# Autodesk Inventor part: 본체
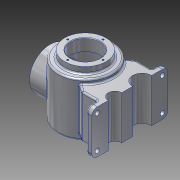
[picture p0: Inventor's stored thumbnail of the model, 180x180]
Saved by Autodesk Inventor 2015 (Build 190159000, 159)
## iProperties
Created: 2018-08
Part Number: 본체
Material: 알루미늄 6061
Document SubType Name: Modeling
Designer: line
Density: 2.7 g/cm^3
Appearance: 알루미늄 - 평지
Mass: 1879.13 g
Surface Area: 1087.48 cm^2
Volume: 695.975 cm^3
Author: line
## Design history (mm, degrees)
sketch "스케치2"
  geometry: L1 (0, 54)-(50, 54); L2 (0, 54)-(0, -54); L3 (0, 54)-(50, 54); L4 (0, 54)-(0, -54); L5 (50, -42.671)-(50, 54); A1 r 116 centre (0, 62) between (0, -54) and (50, -42.671); 1 further point
  constraints: 10 end point, 2 point on circle, 1 centre point, 1 collinear, 1 horizontal
  dimensions: "d14" = 108 vertical distance of L2.end L1.end; "d16" = 50 distance of L1.start L1.end; "d17" = 116 radius of A1; "d18" = 108 distance of L1.start L2.end; "d19" = 50 horizontal distance of L5.start A1.centre; "d20" = 62 distance of point (0, 0) A1.centre; "d21" = 8 vertical distance of L1.end A1.centre
revolve "회전1" sketch "스케치2" stored, may be unused: angle "d22" = 90 deg
sketch "스케치3"
  geometry: C1 r 38 at (0, 0); 1 further point
  constraints: 1 centre point, 1 coincident
  dimensions: "d23" = 76 diameter of C1
extrude "돌출1" join sketch "스케치3" distance "d24" = 12; taper "d25" = 0 deg
sketch "스케치4"
  geometry: C1 r 27 at (0, 0); 1 further point
  constraints: 1 centre point, 1 coincident
  dimensions: "d26" = 54 diameter of C1
extrude "돌출2" cut sketch "스케치4" distance "d27" = 22; taper "d28" = 0 deg
sketch "스케치5" dims "d29" = 65
  geometry: 3 further points
  constraints: 2 vertical alignment, 1 coincident, 2 other
hole "구멍1" sketch "스케치5" at (0, 32.5) diameter "d30" = 3.242; stored, may be unused: countersink angle "d34" = 90 deg, drill point angle "d36" = 118 deg; dims "d31" = 8, "d32" = 4, "d33" = 2, "d35" = 10
sketch "스케치6"
  geometry: L1 (0, 66)-(0, -63.544); L2 (0, 44)-(40, 44); L3 (40, 44)-(40, -36.163); L4 (0, 44)-(40, 44); L5 (40, -36.163)-(40, 44); L6 (-27, 44)-(27, 44) reference; L7 (0, 44)-(0, -44); A1 r 106 centre (0, 62) between (0, -44) and (40, -36.163); 1 further point
  constraints: 12 end point, 2 perpendicular, 2 point on circle, 1 centre point, 1 collinear, 1 point on line, 1 vertical
  dimensions: "d41" = 40 distance of L2.start L2.end; "d42" = 106 radius of A1; "d43" = 80.16313 distance of L2.end L3.end; "d44" = 129.54354 distance of L1.start L1.end; "d45" = 18 distance of L2.start A1.centre; "d46" = 44 distance of L7.end point (0, 0); "d47" = 63.54354 distance of L1.end point (0, 0); "d48" = 40 horizontal distance of A1.centre L2.end
revolve "회전2" sketch "스케치6" stored, may be unused: angle "d49" = 90 deg
node "작업 평면1"
sketch "스케치7"
  geometry: L1 (-1.621, 66)-(1.621, 66) reference; L2 (0, 66)-(0, 4); C1 r 38 at (0, 4); 1 further point
  constraints: 2 end point, 1 centre point, 1 coincident, 1 midpoint, 1 vertical
  dimensions: "d51" = 62 distance of L2.start L2.end; "d52" = 76 diameter of C1
extrude "돌출3" join sketch "스케치7" stored distance "d53" = 22; taper "d54" = 0 deg
sketch "스케치8"
  geometry: C1 r 38 at (0, 0) reference; C2 r 27 at (0, 0); 1 further point
  constraints: 1 centre point, 1 coincident
  dimensions: "d55" = 54 diameter of C2
extrude "돌출4" cut sketch "스케치8" stored distance "d56" = 22; taper "d57" = 0 deg
sketch "스케치9" dims "d58" = 65
  geometry: C1 r 38 at (0, 0) reference; 3 further points
  constraints: 2 vertical alignment, 1 coincident, 2 other
hole "구멍2" sketch "스케치9" at (0, -32.5) diameter "d59" = 3.242; stored, may be unused: countersink angle "d63" = 90 deg, drill point angle "d65" = 118 deg; dims "d60" = 8, "d61" = 4, "d62" = 2, "d64" = 10
chamfer "모따기1" distance "d69" = 1; stored, may be unused: second distance "d70" = 2, angle "d71" = 45 deg
node "작업 평면2"
sketch "스케치11"
  geometry: L1 (0, 0)-(82, 0); L2 (82, 0)-(82, -70); L3 (82, -70)-(72, -70); L4 (72, -70)-(72, -50); L5 (72, -50)-(43.437, -50); L6 (43.437, -50)-(27.371, -38.751); L7 (82, 0)-(82, 70); L8 (82, 70)-(72, 70); L9 (72, 70)-(72, 50); L10 (72, 50)-(43.437, 50); L11 (43.437, 50)-(27.371, 38.751); C1 r 50 at (0, 0) reference; A1 r 47.442 centre (0, 0) between (27.371, -38.751) and (27.371, 38.751); 1 further point
  constraints: 22 end point, 6 perpendicular, 2 point on circle, 2 vertical, 1 centre point, 1 coincident, 1 horizontal
  dimensions: "d86" = 82 distance of L1.start L1.end; "d88" = 70 distance of L1.end L2.end; "d89" = 10 distance of L2.end L3.end; "d90" = 20 distance of L3.end L4.end; "d91" = 35 deg angle of L3 L6; "d92" = 70 distance of L1.end L7.end; "d93" = 10 distance of L7.end L8.end; "d94" = 20 distance of L8.end L9.end; "d95" = 35 deg angle of L11 L8; "d96" = 47.44242 radius of A1; "d97" = 16.0659 horizontal distance of L10.end L11.end; "d98" = 16.0659 horizontal distance of L5.end L6.end
extrude "돌출5" join sketch "스케치11" distance "d99" = 80; taper "d100" = 0 deg
sketch "스케치12"
  geometry: L1 (82, 70)-(82, -70) reference; L2 (82, 70)-(82, -70) reference; C1 r 12.5 at (82, -27.5); C2 r 17.5 at (82, 22.5); 4 further points
  constraints: 2 centre point, 2 coincident, 2 point on line, 2 vertical alignment, 1 midpoint
  dimensions: "d101" = 27.5 distance of point (82, 0) point (82, -27.5); "d102" = 22.5 distance of point (82, 22.5) point (82, 0); "d103" = 25 diameter of C1; "d104" = 35 diameter of C2
extrude "돌출6" cut sketch "스케치12" stored distance "d105" = 80; taper "d106" = 0 deg
fillet "모깎기1" dims "d107" = 3
fillet "모깎기2" dims "d108" = 10
fillet "모깎기3" dims "d109" = 3
sketch "스케치13"
  geometry: C1 r 4 at (10, -20); C2 r 4 at (70, -20); C3 r 4 at (10, 100); C4 r 4 at (70, 100); A1 r 10 centre (10, -20) between (0, -20) and (10, -30) reference; A2 r 10 centre (70, -20) between (70, -30) and (80, -20) reference; A3 r 10 centre (70, 100) between (80, 100) and (70, 110) reference; A4 r 10 centre (10, 100) between (10, 110) and (0, 100) reference; 1 further point
  constraints: 4 centre point, 4 coincident
  dimensions: "d110" = 8 diameter of C1; "d111" = 8 diameter of C2; "d112" = 8 diameter of C3; "d113" = 8 diameter of C4
extrude "돌출7" cut sketch "스케치13" distance "d114" = 20; taper "d115" = 0 deg
node "작업 평면3"
sketch "스케치14"
  geometry: C1 r 32.5 at (0, 0); 1 further point
  constraints: 1 centre point, 1 coincident, 1 other
  dimensions: "d116" = 65 diameter of C1
feature "엠보싱1" sketch "스케치14" dims "d14" = 108, "d16" = 50, "d17" = 116, "d18" = 108, "d19" = 50, "d20" = 62, "d21" = 8, "d117" = 0.5, "d118" = 0
node "솔리드1"
pattern_circular "원형 패턴1" dims angle "d38" = 360 deg
pattern_circular "원형 패턴2" dims angle "d67" = 360 deg
other parameters: "d4" = 116, "d13" = 116, "d50" = -65, "d85" = -8
